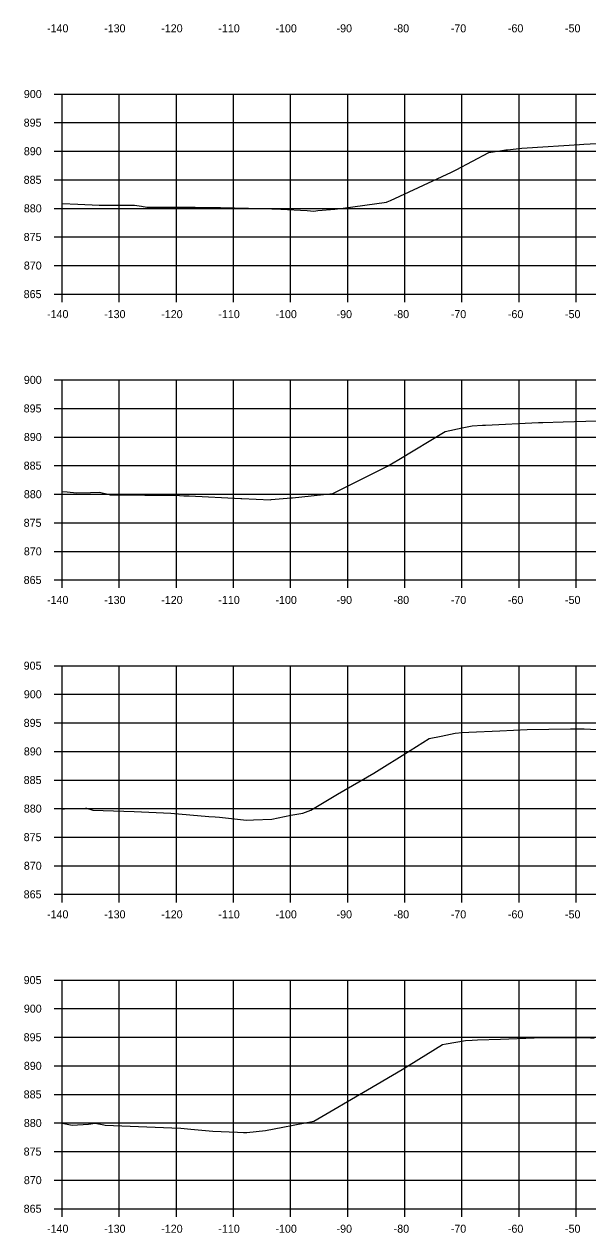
# Model space of a CAD drawing. Extents: x 1098669 to 1198896, y 698679 to 704410.
# Drawn here: x 1112162.5 to 1112261.2, y 701471 to 701682.5 of the extents above; entities that cross this region are included whole.
import ezdxf

# ---------------------------------------------------------------- set-up
doc = ezdxf.new("R2010")
doc.units = 0
for name, color, linetype in [('Proposed Surface', 7, 'Continuous'), ('R_Axis', 7, 'Continuous'), ('R_Axis Annot', 7, 'Continuous'), ('R_Grid', 7, 'Continuous')]:
    doc.layers.add(name, color=color, linetype=linetype)

msp = doc.modelspace()

# ---------------------------------------------------------------- linework, layer by layer
at = {"layer": 'Proposed Surface'}
for points in [[(1112169.18, 701651.14), (1112171.92, 701651.01), (1112175.64, 701650.83), (1112176.09, 701650.84), (1112178.1, 701650.82), (1112180.77, 701650.84), (1112181.86, 701650.84), (1112183.09, 701650.63), (1112184, 701650.5), (1112192.48, 701650.45), (1112196.91, 701650.41), (1112204.23, 701650.23), (1112207.48, 701650.13), (1112212.09, 701649.86), (1112213.25, 701649.8), (1112213.92, 701649.86), (1112216.91, 701650.11), (1112218.39, 701650.3), (1112225.95, 701651.34), (1112226.08, 701651.39), (1112226.65, 701651.65), (1112237.33, 701656.57), (1112238.19, 701657.02), (1112243.91, 701660.04), (1112246.15, 701660.36), (1112246.84, 701660.5), (1112247.14, 701660.52), (1112249.67, 701660.8), (1112250.61, 701660.85), (1112259.78, 701661.46), (1112260.5, 701661.49), (1112269.52, 701661.94)], [(1112169.18, 701600.76), (1112170.05, 701600.66), (1112171.71, 701600.52), (1112174.13, 701600.56), (1112175.69, 701600.59), (1112177.14, 701600.24), (1112177.57, 701600.12), (1112189.73, 701600.02), (1112190.5, 701600), (1112191.39, 701599.95), (1112200.45, 701599.51), (1112200.63, 701599.5), (1112205.68, 701599.3), (1112205.75, 701599.31), (1112209.27, 701599.61), (1112209.52, 701599.64), (1112216.58, 701600.4), (1112218.31, 701601.26), (1112226.15, 701605.15), (1112228.13, 701606.32), (1112236.22, 701611.23), (1112239.23, 701611.84), (1112240.96, 701612.2), (1112242.78, 701612.31), (1112243.3, 701612.35), (1112252.58, 701612.78), (1112253.33, 701612.81), (1112256.91, 701612.92), (1112262.87, 701613.1)], [(1112169.18, 701545.19), (1112169.59, 701545.2), (1112173.23, 701545.36), (1112173.42, 701545.31), (1112174.57, 701544.99), (1112181.75, 701544.77), (1112188.19, 701544.44), (1112194.88, 701543.9), (1112195.97, 701543.83), (1112196.71, 701543.77), (1112201.47, 701543.24), (1112202.7, 701543.31), (1112205.86, 701543.43), (1112209.22, 701544.09), (1112211.29, 701544.43), (1112212.71, 701545), (1112217.36, 701547.8), (1112223.74, 701551.43), (1112230.1, 701555.43), (1112233.44, 701557.53), (1112235.51, 701557.95), (1112238, 701558.48), (1112239.22, 701558.56), (1112240.4, 701558.65), (1112245.83, 701558.88), (1112250.59, 701559.1), (1112258.18, 701559.2), (1112259.87, 701559.23), (1112260.6, 701559.21), (1112263.84, 701559.05)], [(1112169.18, 701490.2), (1112170.05, 701490.03), (1112170.91, 701489.89), (1112173.81, 701490.08), (1112174.97, 701490.2), (1112176.49, 701489.95), (1112176.7, 701489.9), (1112188.4, 701489.4), (1112189.96, 701489.35), (1112191.73, 701489.2), (1112195.55, 701488.82), (1112199.87, 701488.63), (1112200.9, 701488.57), (1112201.48, 701488.61), (1112204.75, 701488.93), (1112207.83, 701489.53), (1112213.24, 701490.57), (1112222.66, 701496.06), (1112228.69, 701499.61), (1112229.95, 701500.39), (1112235.79, 701503.98), (1112236.39, 701504.1), (1112239.81, 701504.71), (1112240.98, 701504.74), (1112241.92, 701504.79), (1112245.93, 701504.95), (1112251.82, 701505.15), (1112255.4, 701505.19), (1112260.96, 701505.24), (1112262.31, 701505.12)]]:
    msp.add_lwpolyline(points, dxfattribs=at)
at = {"layer": 'R_Axis'}
for p, q in [((1112167.78, 701670.26), (1112169.18, 701670.26)), ((1112169.18, 701635.26), (1112169.18, 701670.26)), ((1112167.78, 701665.26), (1112169.18, 701665.26)), ((1112167.78, 701660.26), (1112169.18, 701660.26)), ((1112167.78, 701655.26), (1112169.18, 701655.26)), ((1112167.78, 701650.26), (1112169.18, 701650.26)), ((1112167.78, 701645.26), (1112169.18, 701645.26)), ((1112167.78, 701640.26), (1112169.18, 701640.26)), ((1112167.78, 701635.26), (1112169.18, 701635.26)), ((1112169.18, 701635.26), (1112449.18, 701635.26)), ((1112169.18, 701633.86), (1112169.18, 701635.26)), ((1112179.18, 701633.86), (1112179.18, 701635.26)), ((1112189.18, 701633.86), (1112189.18, 701635.26)), ((1112199.18, 701633.86), (1112199.18, 701635.26)), ((1112209.18, 701633.86), (1112209.18, 701635.26)), ((1112219.18, 701633.86), (1112219.18, 701635.26)), ((1112229.18, 701633.86), (1112229.18, 701635.26)), ((1112239.18, 701633.86), (1112239.18, 701635.26)), ((1112249.18, 701633.86), (1112249.18, 701635.26)), ((1112259.18, 701633.86), (1112259.18, 701635.26)), ((1112167.78, 701620.26), (1112169.18, 701620.26)), ((1112169.18, 701585.26), (1112169.18, 701620.26)), ((1112167.78, 701615.26), (1112169.18, 701615.26)), ((1112167.78, 701610.26), (1112169.18, 701610.26)), ((1112167.78, 701605.26), (1112169.18, 701605.26)), ((1112167.78, 701600.26), (1112169.18, 701600.26)), ((1112167.78, 701595.26), (1112169.18, 701595.26)), ((1112167.78, 701590.26), (1112169.18, 701590.26)), ((1112167.78, 701585.26), (1112169.18, 701585.26)), ((1112169.18, 701585.26), (1112449.18, 701585.26)), ((1112169.18, 701583.86), (1112169.18, 701585.26)), ((1112179.18, 701583.86), (1112179.18, 701585.26)), ((1112189.18, 701583.86), (1112189.18, 701585.26)), ((1112199.18, 701583.86), (1112199.18, 701585.26)), ((1112209.18, 701583.86), (1112209.18, 701585.26)), ((1112219.18, 701583.86), (1112219.18, 701585.26)), ((1112229.18, 701583.86), (1112229.18, 701585.26)), ((1112239.18, 701583.86), (1112239.18, 701585.26)), ((1112249.18, 701583.86), (1112249.18, 701585.26)), ((1112259.18, 701583.86), (1112259.18, 701585.26)), ((1112167.78, 701570.26), (1112169.18, 701570.26)), ((1112169.18, 701530.26), (1112169.18, 701570.26)), ((1112167.78, 701565.26), (1112169.18, 701565.26)), ((1112167.78, 701560.26), (1112169.18, 701560.26)), ((1112167.78, 701555.26), (1112169.18, 701555.26)), ((1112167.78, 701550.26), (1112169.18, 701550.26)), ((1112167.78, 701545.26), (1112169.18, 701545.26)), ((1112167.78, 701540.26), (1112169.18, 701540.26)), ((1112167.78, 701535.26), (1112169.18, 701535.26)), ((1112167.78, 701530.26), (1112169.18, 701530.26)), ((1112169.18, 701530.26), (1112449.18, 701530.26)), ((1112169.18, 701528.86), (1112169.18, 701530.26)), ((1112179.18, 701528.86), (1112179.18, 701530.26)), ((1112189.18, 701528.86), (1112189.18, 701530.26)), ((1112199.18, 701528.86), (1112199.18, 701530.26)), ((1112209.18, 701528.86), (1112209.18, 701530.26)), ((1112219.18, 701528.86), (1112219.18, 701530.26)), ((1112229.18, 701528.86), (1112229.18, 701530.26)), ((1112239.18, 701528.86), (1112239.18, 701530.26)), ((1112249.18, 701528.86), (1112249.18, 701530.26)), ((1112259.18, 701528.86), (1112259.18, 701530.26)), ((1112167.78, 701515.26), (1112169.18, 701515.26)), ((1112169.18, 701475.26), (1112169.18, 701515.26)), ((1112167.78, 701510.26), (1112169.18, 701510.26)), ((1112167.78, 701505.26), (1112169.18, 701505.26)), ((1112167.78, 701500.26), (1112169.18, 701500.26)), ((1112167.78, 701495.26), (1112169.18, 701495.26)), ((1112167.78, 701490.26), (1112169.18, 701490.26)), ((1112167.78, 701485.26), (1112169.18, 701485.26)), ((1112167.78, 701480.26), (1112169.18, 701480.26)), ((1112167.78, 701475.26), (1112169.18, 701475.26)), ((1112169.18, 701475.26), (1112449.18, 701475.26)), ((1112169.18, 701473.86), (1112169.18, 701475.26)), ((1112179.18, 701473.86), (1112179.18, 701475.26)), ((1112189.18, 701473.86), (1112189.18, 701475.26)), ((1112199.18, 701473.86), (1112199.18, 701475.26)), ((1112209.18, 701473.86), (1112209.18, 701475.26)), ((1112219.18, 701473.86), (1112219.18, 701475.26)), ((1112229.18, 701473.86), (1112229.18, 701475.26)), ((1112239.18, 701473.86), (1112239.18, 701475.26)), ((1112249.18, 701473.86), (1112249.18, 701475.26)), ((1112259.18, 701473.86), (1112259.18, 701475.26))]:
    msp.add_line(p, q, dxfattribs=at)
at = {"layer": 'R_Grid'}
for p, q in [((1112169.18, 701670.26), (1112449.18, 701670.26)), ((1112169.18, 701635.26), (1112169.18, 701670.26)), ((1112179.18, 701635.26), (1112179.18, 701670.26)), ((1112189.18, 701635.26), (1112189.18, 701670.26)), ((1112199.18, 701635.26), (1112199.18, 701670.26)), ((1112209.18, 701635.26), (1112209.18, 701670.26)), ((1112219.18, 701635.26), (1112219.18, 701670.26)), ((1112229.18, 701635.26), (1112229.18, 701670.26)), ((1112239.18, 701635.26), (1112239.18, 701670.26)), ((1112249.18, 701635.26), (1112249.18, 701670.26)), ((1112259.18, 701635.26), (1112259.18, 701670.26)), ((1112169.18, 701665.26), (1112449.18, 701665.26)), ((1112169.18, 701660.26), (1112449.18, 701660.26)), ((1112169.18, 701655.26), (1112449.18, 701655.26)), ((1112169.18, 701650.26), (1112449.18, 701650.26)), ((1112169.18, 701645.26), (1112449.18, 701645.26)), ((1112169.18, 701640.26), (1112449.18, 701640.26)), ((1112169.18, 701635.26), (1112449.18, 701635.26)), ((1112169.18, 701620.26), (1112449.18, 701620.26)), ((1112169.18, 701585.26), (1112169.18, 701620.26)), ((1112179.18, 701585.26), (1112179.18, 701620.26)), ((1112189.18, 701585.26), (1112189.18, 701620.26)), ((1112199.18, 701585.26), (1112199.18, 701620.26)), ((1112209.18, 701585.26), (1112209.18, 701620.26)), ((1112219.18, 701585.26), (1112219.18, 701620.26)), ((1112229.18, 701585.26), (1112229.18, 701620.26)), ((1112239.18, 701585.26), (1112239.18, 701620.26)), ((1112249.18, 701585.26), (1112249.18, 701620.26)), ((1112259.18, 701585.26), (1112259.18, 701620.26)), ((1112169.18, 701615.26), (1112449.18, 701615.26)), ((1112169.18, 701610.26), (1112449.18, 701610.26)), ((1112169.18, 701605.26), (1112449.18, 701605.26)), ((1112169.18, 701600.26), (1112449.18, 701600.26)), ((1112169.18, 701595.26), (1112449.18, 701595.26)), ((1112169.18, 701590.26), (1112449.18, 701590.26)), ((1112169.18, 701585.26), (1112449.18, 701585.26)), ((1112169.18, 701570.26), (1112449.18, 701570.26)), ((1112169.18, 701530.26), (1112169.18, 701570.26)), ((1112179.18, 701530.26), (1112179.18, 701570.26)), ((1112189.18, 701530.26), (1112189.18, 701570.26)), ((1112199.18, 701530.26), (1112199.18, 701570.26)), ((1112209.18, 701530.26), (1112209.18, 701570.26)), ((1112219.18, 701530.26), (1112219.18, 701570.26)), ((1112229.18, 701530.26), (1112229.18, 701570.26)), ((1112239.18, 701530.26), (1112239.18, 701570.26)), ((1112249.18, 701530.26), (1112249.18, 701570.26)), ((1112259.18, 701530.26), (1112259.18, 701570.26)), ((1112169.18, 701565.26), (1112449.18, 701565.26)), ((1112169.18, 701560.26), (1112449.18, 701560.26)), ((1112169.18, 701555.26), (1112449.18, 701555.26)), ((1112169.18, 701550.26), (1112449.18, 701550.26)), ((1112169.18, 701545.26), (1112449.18, 701545.26)), ((1112169.18, 701540.26), (1112449.18, 701540.26)), ((1112169.18, 701535.26), (1112449.18, 701535.26)), ((1112169.18, 701530.26), (1112449.18, 701530.26)), ((1112169.18, 701515.26), (1112449.18, 701515.26)), ((1112169.18, 701475.26), (1112169.18, 701515.26)), ((1112179.18, 701475.26), (1112179.18, 701515.26)), ((1112189.18, 701475.26), (1112189.18, 701515.26)), ((1112199.18, 701475.26), (1112199.18, 701515.26)), ((1112209.18, 701475.26), (1112209.18, 701515.26)), ((1112219.18, 701475.26), (1112219.18, 701515.26)), ((1112229.18, 701475.26), (1112229.18, 701515.26)), ((1112239.18, 701475.26), (1112239.18, 701515.26)), ((1112249.18, 701475.26), (1112249.18, 701515.26)), ((1112259.18, 701475.26), (1112259.18, 701515.26)), ((1112169.18, 701510.26), (1112449.18, 701510.26)), ((1112169.18, 701505.26), (1112449.18, 701505.26)), ((1112169.18, 701500.26), (1112449.18, 701500.26)), ((1112169.18, 701495.26), (1112449.18, 701495.26)), ((1112169.18, 701490.26), (1112449.18, 701490.26)), ((1112169.18, 701485.26), (1112449.18, 701485.26)), ((1112169.18, 701480.26), (1112449.18, 701480.26)), ((1112169.18, 701475.26), (1112449.18, 701475.26))]:
    msp.add_line(p, q, dxfattribs=at)

# ---------------------------------------------------------------- texts
at = {"layer": 'R_Axis Annot'}
for s, p in [('-140', (1112166.52, 701681.06)), ('-130', (1112176.52, 701681.06)), ('-120', (1112186.52, 701681.06)), ('-110', (1112196.52, 701681.06)), ('-100', (1112206.52, 701681.06)), ('-90', (1112217.22, 701681.06)), ('-80', (1112227.22, 701681.06)), ('-70', (1112237.22, 701681.06)), ('-60', (1112247.22, 701681.06)), ('-50', (1112257.22, 701681.06)), ('900', (1112162.46, 701669.56)), ('895', (1112162.43, 701664.56)), ('890', (1112162.46, 701659.56)), ('885', (1112162.43, 701654.56)), ('880', (1112162.46, 701649.56)), ('875', (1112162.43, 701644.56)), ('870', (1112162.46, 701639.56)), ('865', (1112162.43, 701634.56)), ('-140', (1112166.52, 701631.06)), ('-130', (1112176.52, 701631.06)), ('-120', (1112186.52, 701631.06)), ('-110', (1112196.52, 701631.06)), ('-100', (1112206.52, 701631.06)), ('-90', (1112217.22, 701631.06)), ('-80', (1112227.22, 701631.06)), ('-70', (1112237.22, 701631.06)), ('-60', (1112247.22, 701631.06)), ('-50', (1112257.22, 701631.06)), ('900', (1112162.46, 701619.56)), ('895', (1112162.43, 701614.56)), ('890', (1112162.46, 701609.56)), ('885', (1112162.43, 701604.56)), ('880', (1112162.46, 701599.56)), ('875', (1112162.43, 701594.56)), ('870', (1112162.46, 701589.56)), ('865', (1112162.43, 701584.56)), ('-140', (1112166.52, 701581.06)), ('-130', (1112176.52, 701581.06)), ('-120', (1112186.52, 701581.06)), ('-110', (1112196.52, 701581.06)), ('-100', (1112206.52, 701581.06)), ('-90', (1112217.22, 701581.06)), ('-80', (1112227.22, 701581.06)), ('-70', (1112237.22, 701581.06)), ('-60', (1112247.22, 701581.06)), ('-50', (1112257.22, 701581.06)), ('905', (1112162.43, 701569.56)), ('900', (1112162.46, 701564.56)), ('895', (1112162.43, 701559.56)), ('890', (1112162.46, 701554.56)), ('885', (1112162.43, 701549.56)), ('880', (1112162.46, 701544.56)), ('875', (1112162.43, 701539.56)), ('870', (1112162.46, 701534.56)), ('865', (1112162.43, 701529.56)), ('-140', (1112166.52, 701526.06)), ('-130', (1112176.52, 701526.06)), ('-120', (1112186.52, 701526.06)), ('-110', (1112196.52, 701526.06)), ('-100', (1112206.52, 701526.06)), ('-90', (1112217.22, 701526.06)), ('-80', (1112227.22, 701526.06)), ('-70', (1112237.22, 701526.06)), ('-60', (1112247.22, 701526.06)), ('-50', (1112257.22, 701526.06)), ('905', (1112162.43, 701514.56)), ('900', (1112162.46, 701509.56)), ('895', (1112162.43, 701504.56)), ('890', (1112162.46, 701499.56)), ('885', (1112162.43, 701494.56)), ('880', (1112162.46, 701489.56)), ('875', (1112162.43, 701484.56)), ('870', (1112162.46, 701479.56)), ('865', (1112162.43, 701474.56)), ('-140', (1112166.52, 701471.06)), ('-130', (1112176.52, 701471.06)), ('-120', (1112186.52, 701471.06)), ('-110', (1112196.52, 701471.06)), ('-100', (1112206.52, 701471.06)), ('-90', (1112217.22, 701471.06)), ('-80', (1112227.22, 701471.06)), ('-70', (1112237.22, 701471.06)), ('-60', (1112247.22, 701471.06)), ('-50', (1112257.22, 701471.06))]:
    msp.add_text(s, height=1.4, dxfattribs=at).set_placement(p)

doc.saveas('drawing.dxf')
